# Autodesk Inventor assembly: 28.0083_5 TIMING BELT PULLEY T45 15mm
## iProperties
Created: 2006-12
Part Number: 28.0083_5 TIMING BELT PULLEY T45 15mm
Document SubType Name: Assembly
Designer: Andy Moles
Author: Andy Moles
